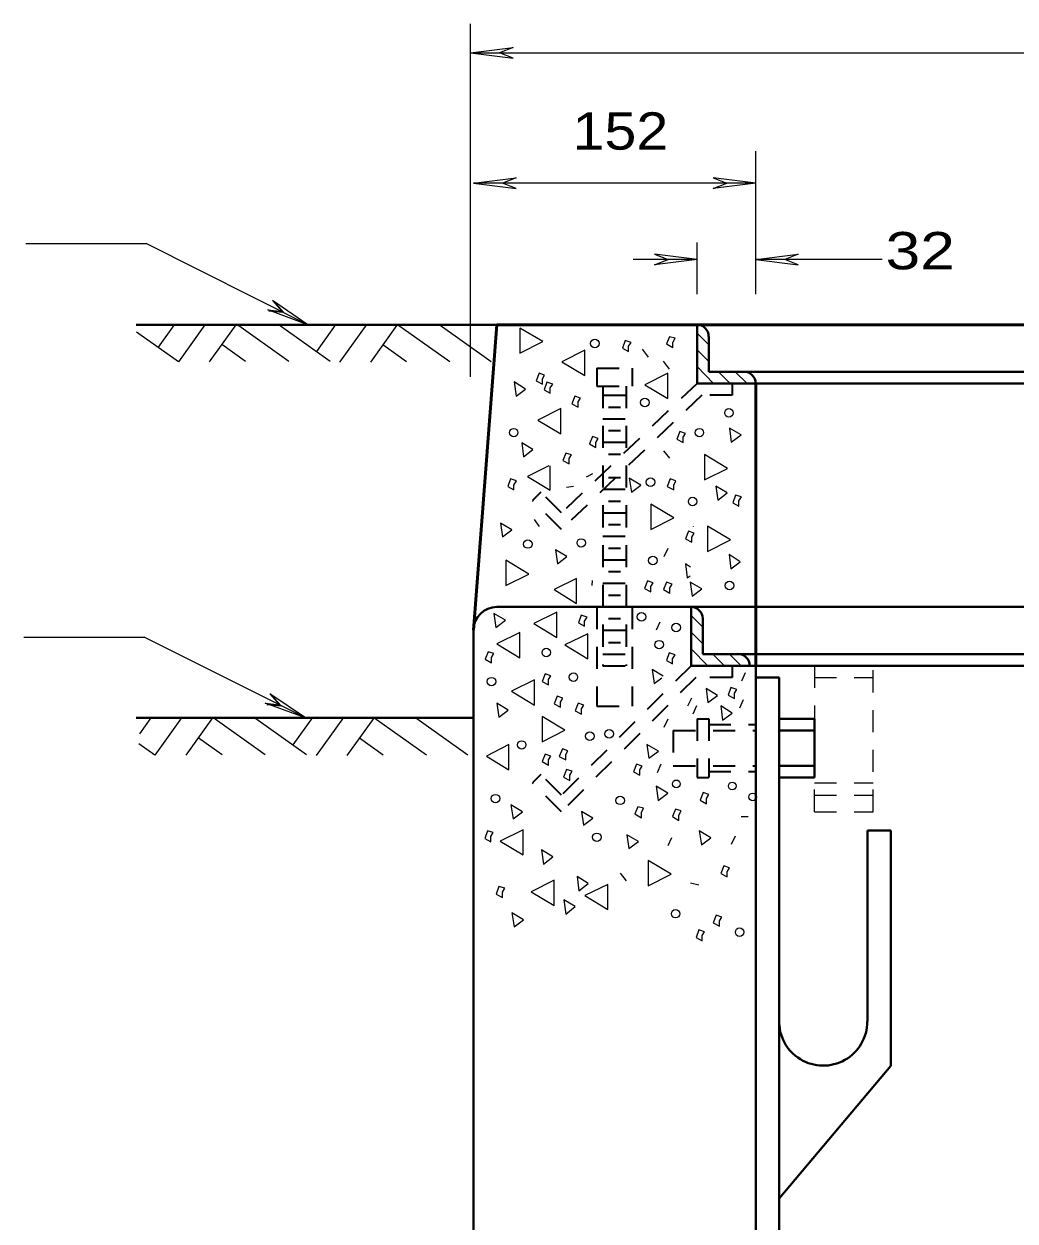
# Model space of a CAD drawing. Extents: x 312583 to 312853, y 144419 to 144586.
# Drawn here: x 312745.46 to 312765.66, y 144474.02 to 144498.4 of the extents above; entities that cross this region are included whole.
import ezdxf

# ---------------------------------------------------------------- set-up
doc = ezdxf.new("R2010")
doc.units = 0
doc.header["$LTSCALE"] = 0.3
doc.linetypes.add('SHORT_DASHED', pattern=[2.7, 1.5, -1.2])
doc.layers.add('1', color=7, linetype='Continuous', lineweight=40)
doc.layers.add('2', color=7, linetype='Continuous', lineweight=13)

msp = doc.modelspace()

# ---------------------------------------------------------------- linework, layer by layer
at = {"layer": '1'}
for p, q in [((312747.749, 144492.2754), (312755.1014, 144492.2754)), ((312759.18, 144492.2754), (312759.18, 144491.0794)), ((312759.4177, 144492.0377), (312759.4177, 144491.3171)), ((312759.4177, 144491.3171), (312778.5844, 144491.3171)), ((312759.18, 144491.0794), (312778.822, 144491.0794)), ((312755.1014, 144486.5254), (312782.893, 144486.5254)), ((312759.0574, 144486.5254), (312759.0574, 144485.3294)), ((312759.295, 144486.2877), (312759.295, 144485.5671)), ((312759.295, 144485.5671), (312778.5844, 144485.5671)), ((312759.0574, 144485.3294), (312778.822, 144485.3294)), ((312760.376, 144485.3294), (312760.376, 144443.4004)), ((312760.376, 144485.0917), (312760.8514, 144485.0917)), ((312760.8514, 144485.0917), (312760.8514, 144454.4251)), ((312747.749, 144484.2637), (312754.626, 144484.2637)), ((312760.8514, 144484.2484), (312761.572, 144484.2484)), ((312761.572, 144484.2484), (312761.572, 144483.0524)), ((312760.8514, 144484.0107), (312761.572, 144484.0107)), ((312760.8514, 144483.2901), (312761.572, 144483.2901)), ((312760.8514, 144483.0524), (312761.572, 144483.0524)), ((312762.653, 144481.9714), (312762.653, 144478.0844)), ((312762.653, 144481.9714), (312763.1284, 144481.9714)), ((312763.1284, 144481.9714), (312763.1284, 144477.1797)), ((312760.8514, 144474.4734), (312763.1284, 144477.1797))]:
    msp.add_line(p, q, dxfattribs=at)
at = {"layer": '1', "lineweight": 53}
for p, q in [((312754.626, 144486.0501), (312755.1014, 144492.2754)), ((312755.1014, 144492.2754), (312782.893, 144492.2754)), ((312760.376, 144491.0794), (312760.376, 144485.3294))]:
    msp.add_line(p, q, dxfattribs=at)
at = {"layer": '1', "lineweight": 13}
for p, q in [((312758.0607, 144491.7771), (312758.1834, 144491.6161)), ((312758.49, 144491.5317), (312758.6127, 144491.3707)), ((312758.4977, 144489.7071), (312758.6204, 144489.5537)), ((312756.19, 144488.9021), (312756.19, 144489.4004)), ((312756.926, 144489.1781), (312757.0564, 144489.2471)), ((312756.5197, 144488.9634), (312756.6654, 144488.9864)), ((312755.8604, 144488.3041), (312755.96, 144488.1661)), ((312759.1034, 144488.1737), (312759.1034, 144488.1661)), ((312758.582, 144487.7137), (312758.5054, 144487.5451)), ((312758.9807, 144487.1157), (312759.042, 144487.1617)), ((312757.041, 144486.9624), (312757.0487, 144487.0621)), ((312758.421, 144486.2187), (312758.3444, 144486.0501)), ((312760.1614, 144485.1837), (312760.0847, 144485.0151)), ((312758.306, 144484.9691), (312758.4594, 144485.0841)), ((312759.065, 144484.6701), (312758.9884, 144484.5014)), ((312759.1724, 144484.5091), (312759.0957, 144484.3404)), ((312760.123, 144484.6317), (312760.0464, 144484.4631)), ((312758.582, 144484.2407), (312758.5054, 144484.0721)), ((312758.444, 144483.3207), (312758.3674, 144483.1444)), ((312760.077, 144482.2551), (312760.2227, 144482.2551)), ((312758.6587, 144481.8257), (312758.582, 144481.6571)), ((312759.9544, 144481.8564), (312759.8777, 144481.6877)), ((312757.616, 144481.1051), (312757.7387, 144480.9441)), ((312759.0497, 144480.9057), (312759.2184, 144480.8674))]:
    msp.add_line(p, q, dxfattribs=at)
at = {"layer": '1', "linetype": 'SHORT_DASHED', "lineweight": 35}
for p, q in [((312757.1407, 144491.3861), (312757.1407, 144491.0257)), ((312757.1407, 144491.3861), (312757.8614, 144491.3861)), ((312757.8614, 144491.3861), (312757.8614, 144491.0257)), ((312759.18, 144491.0794), (312756.42, 144488.4421)), ((312757.1407, 144491.0257), (312757.8614, 144491.0257)), ((312757.2634, 144491.0257), (312757.2634, 144485.3294)), ((312757.7387, 144491.0257), (312757.7387, 144485.3294)), ((312759.893, 144491.0794), (312759.893, 144490.8417)), ((312759.2797, 144490.8417), (312756.42, 144488.1047)), ((312757.2634, 144490.8417), (312757.7387, 144490.8417)), ((312759.893, 144490.8417), (312759.2797, 144490.8417)), ((312757.3784, 144490.5964), (312757.6237, 144490.5964)), ((312757.2634, 144490.3587), (312757.7387, 144490.3587)), ((312757.3784, 144490.1211), (312757.6237, 144490.1211)), ((312757.2634, 144489.8834), (312757.7387, 144489.8834)), ((312757.3784, 144489.6381), (312757.6237, 144489.6381)), ((312757.3784, 144489.1627), (312757.6237, 144489.1627)), ((312755.9984, 144488.8637), (312755.8297, 144488.6951)), ((312756.42, 144488.4421), (312755.9984, 144488.8637)), ((312757.2634, 144488.9251), (312757.7387, 144488.9251)), ((312756.42, 144488.1047), (312755.8297, 144488.6951)), ((312757.3784, 144488.6797), (312757.6237, 144488.6797)), ((312757.2634, 144488.4421), (312757.7387, 144488.4421)), ((312757.3784, 144488.2044), (312757.6237, 144488.2044)), ((312757.2634, 144487.9667), (312757.7387, 144487.9667)), ((312757.3784, 144487.7214), (312757.6237, 144487.7214)), ((312757.2634, 144487.4837), (312757.7387, 144487.4837)), ((312757.3784, 144487.2461), (312757.6237, 144487.2461)), ((312757.2634, 144487.0084), (312757.7387, 144487.0084)), ((312757.3784, 144486.7631), (312757.6237, 144486.7631)), ((312757.1407, 144486.5254), (312757.1407, 144484.5014)), ((312757.2634, 144486.5254), (312757.7387, 144486.5254)), ((312757.8614, 144486.5254), (312757.8614, 144484.5014)), ((312757.3784, 144486.2877), (312757.6237, 144486.2877)), ((312757.2634, 144486.0501), (312757.7387, 144486.0501)), ((312757.3784, 144485.8047), (312757.6237, 144485.8047)), ((312757.2634, 144485.5671), (312757.7387, 144485.5671)), ((312759.0574, 144485.3294), (312756.42, 144482.6921)), ((312757.2634, 144485.3294), (312757.7387, 144485.3294)), ((312759.893, 144485.3294), (312759.893, 144485.0917)), ((312759.157, 144485.0917), (312756.42, 144482.3547)), ((312759.893, 144485.0917), (312759.157, 144485.0917)), ((312757.1407, 144484.5014), (312757.8614, 144484.5014)), ((312759.18, 144484.2484), (312759.18, 144483.0524)), ((312759.18, 144484.2484), (312759.4177, 144484.2484)), ((312759.4177, 144484.2484), (312759.4177, 144483.0524)), ((312758.697, 144484.0107), (312758.697, 144483.2901)), ((312758.697, 144484.0107), (312760.376, 144484.0107)), ((312759.4177, 144484.1334), (312760.376, 144484.1334)), ((312758.697, 144483.2901), (312760.376, 144483.2901)), ((312755.9984, 144483.1137), (312755.8297, 144482.9451)), ((312756.42, 144482.3547), (312755.8297, 144482.9451)), ((312756.42, 144482.6921), (312755.9984, 144483.1137)), ((312759.18, 144483.0524), (312759.4177, 144483.0524)), ((312759.4177, 144483.1751), (312760.376, 144483.1751))]:
    msp.add_line(p, q, dxfattribs=at)
at = {"layer": '1', "linetype": 'SHORT_DASHED', "lineweight": 25}
for p, q in [((312761.572, 144485.3294), (312761.572, 144484.2484)), ((312762.768, 144482.3547), (312762.768, 144485.3294)), ((312761.572, 144485.0917), (312762.768, 144485.0917)), ((312761.572, 144482.3547), (312761.572, 144483.0524)), ((312761.572, 144482.9451), (312762.768, 144482.9451)), ((312761.572, 144482.6921), (312762.768, 144482.6921)), ((312761.572, 144482.3547), (312762.768, 144482.3547))]:
    msp.add_line(p, q, dxfattribs=at)
at = {"layer": '1', "lineweight": 13}
for points in [[(312755.569, 144492.2064), (312755.569, 144491.6927), (312756.0367, 144491.9304)], [(312758.6894, 144491.9151), (312758.7354, 144491.9994), (312758.6204, 144492.0301), (312758.559, 144491.8844), (312758.6894, 144491.8077)], [(312756.8954, 144491.2404), (312756.8954, 144491.7541), (312756.4277, 144491.5164)], [(312757.7847, 144491.8384), (312757.8384, 144491.9151), (312757.7157, 144491.9534), (312757.662, 144491.8001), (312757.7847, 144491.7311)], [(312756.029, 144491.1714), (312756.075, 144491.2481), (312755.96, 144491.2864), (312755.8987, 144491.1331), (312756.029, 144491.0641)], [(312758.582, 144490.7727), (312758.582, 144491.2864), (312758.1144, 144491.0487)], [(312755.4924, 144490.8187), (312755.684, 144490.9644), (312755.454, 144491.1101)], [(312756.19, 144490.9874), (312756.2437, 144491.0641), (312756.121, 144491.1024), (312756.0674, 144490.9491), (312756.19, 144490.8801)], [(312756.7574, 144490.7037), (312756.8034, 144490.7804), (312756.6884, 144490.8187), (312756.627, 144490.6654), (312756.7574, 144490.5964)], [(312756.4047, 144490.0521), (312756.4047, 144490.5657), (312755.937, 144490.3281)], [(312758.8964, 144489.9831), (312758.9424, 144490.0597), (312758.8274, 144490.0981), (312758.766, 144489.9447), (312758.8964, 144489.8757)], [(312759.8777, 144489.8834), (312760.077, 144490.0291), (312759.8394, 144490.1671)], [(312755.6457, 144489.5844), (312755.8374, 144489.7301), (312755.6074, 144489.8681)], [(312757.1177, 144489.8757), (312757.1637, 144489.9601), (312757.0487, 144489.9984), (312756.9874, 144489.8451), (312757.1177, 144489.7761)], [(312756.5734, 144489.5461), (312756.6194, 144489.6227), (312756.5044, 144489.6611), (312756.443, 144489.5077), (312756.5734, 144489.4387)], [(312759.3334, 144489.6304), (312759.3334, 144489.1167), (312759.801, 144489.3467)], [(312755.4464, 144489.0094), (312755.5, 144489.0937), (312755.3774, 144489.1321), (312755.3237, 144488.9787), (312755.4464, 144488.9097)], [(312757.846, 144488.8637), (312758.0377, 144489.0094), (312757.8, 144489.1474)], [(312758.7047, 144489.0094), (312758.7507, 144489.0937), (312758.6357, 144489.1321), (312758.5744, 144488.9787), (312758.7047, 144488.9097)], [(312759.6017, 144488.7027), (312759.7934, 144488.8484), (312759.5634, 144488.9864)], [(312760.031, 144488.6874), (312760.0847, 144488.7717), (312759.962, 144488.8024), (312759.9084, 144488.6491), (312760.031, 144488.5801)], [(312758.237, 144488.6184), (312758.237, 144488.1047), (312758.7047, 144488.3424)], [(312755.2164, 144487.9514), (312755.408, 144488.0971), (312755.178, 144488.2351)], [(312759.0727, 144487.9437), (312759.1187, 144488.0281), (312759.0037, 144488.0664), (312758.9424, 144487.9131), (312759.0727, 144487.8441)], [(312759.3947, 144488.1737), (312759.3947, 144487.6524), (312759.8624, 144487.8901)], [(312756.3357, 144487.4071), (312756.5274, 144487.5527), (312756.2974, 144487.6907)], [(312759.87, 144487.2997), (312760.0617, 144487.4454), (312759.8317, 144487.5911)], [(312755.2854, 144487.4761), (312755.2854, 144486.9624), (312755.753, 144487.1924)], [(312756.7267, 144486.5944), (312756.7267, 144487.1081), (312756.2667, 144486.8781)], [(312758.237, 144486.9394), (312758.283, 144487.0161), (312758.168, 144487.0544), (312758.1067, 144486.9011), (312758.237, 144486.8321)], [(312758.628, 144486.9164), (312758.674, 144486.9931), (312758.559, 144487.0314), (312758.4977, 144486.8781), (312758.628, 144486.8091)], [(312759.0804, 144486.7477), (312759.2797, 144486.8934), (312759.042, 144487.0314)], [(312755.0784, 144486.1037), (312755.2777, 144486.2571), (312755.04, 144486.3951)], [(312756.3204, 144485.9044), (312756.3204, 144486.4181), (312755.8527, 144486.1881)], [(312756.8877, 144486.2341), (312756.9414, 144486.3184), (312756.8187, 144486.3567), (312756.765, 144486.2034), (312756.8877, 144486.1344)], [(312755.569, 144485.4904), (312755.569, 144486.0041), (312755.1014, 144485.7741)], [(312756.9567, 144485.4674), (312756.9567, 144485.9811), (312756.489, 144485.7511)], [(312754.994, 144485.4981), (312755.04, 144485.5747), (312754.925, 144485.6131), (312754.8637, 144485.4597), (312754.994, 144485.3907)], [(312758.6817, 144485.4674), (312758.7354, 144485.5517), (312758.6127, 144485.5901), (312758.559, 144485.4367), (312758.6817, 144485.3677)], [(312756.1517, 144485.0457), (312756.1977, 144485.1224), (312756.0827, 144485.1607), (312756.0214, 144485.0074), (312756.1517, 144484.9384)], [(312755.868, 144484.5244), (312755.868, 144485.0381), (312755.4004, 144484.8081)], [(312759.9467, 144484.7697), (312759.9927, 144484.8464), (312759.87, 144484.8847), (312759.8164, 144484.7314), (312759.9467, 144484.6624)], [(312756.397, 144484.5857), (312756.443, 144484.6701), (312756.328, 144484.7084), (312756.2667, 144484.5551), (312756.397, 144484.4861)], [(312759.4024, 144484.5781), (312759.594, 144484.7237), (312759.364, 144484.8617)], [(312755.1397, 144484.2791), (312755.3314, 144484.4247), (312755.1014, 144484.5627)], [(312756.8264, 144484.4477), (312756.8724, 144484.5244), (312756.7574, 144484.5627), (312756.696, 144484.4094), (312756.8264, 144484.3404)], [(312759.7014, 144484.2177), (312759.893, 144484.3634), (312759.663, 144484.5091)], [(312756.0214, 144484.2944), (312756.0214, 144483.7807), (312756.489, 144484.0184)], [(312755.3467, 144483.2057), (312755.3467, 144483.7271), (312754.8867, 144483.4894)], [(312758.1987, 144483.4434), (312758.398, 144483.5891), (312758.1604, 144483.7271)], [(312756.1517, 144483.4127), (312756.1977, 144483.4894), (312756.0827, 144483.5277), (312756.0214, 144483.3744), (312756.1517, 144483.3054)], [(312756.5044, 144483.5201), (312756.5504, 144483.5967), (312756.4354, 144483.6351), (312756.374, 144483.4817), (312756.5044, 144483.4127)], [(312756.5887, 144483.0984), (312756.6347, 144483.1827), (312756.5197, 144483.2134), (312756.4584, 144483.0601), (312756.5887, 144482.9911)], [(312758.0147, 144483.2057), (312758.0607, 144483.2824), (312757.9457, 144483.3207), (312757.8844, 144483.1674), (312758.0147, 144483.0984)], [(312758.3904, 144482.5847), (312758.582, 144482.7304), (312758.3444, 144482.8761)], [(312759.3717, 144482.6231), (312759.4177, 144482.7074), (312759.3027, 144482.7457), (312759.2414, 144482.5924), (312759.3717, 144482.5157)], [(312755.431, 144482.2091), (312755.6227, 144482.3547), (312755.385, 144482.4927)], [(312758.0454, 144482.3394), (312758.0914, 144482.4237), (312757.9764, 144482.4544), (312757.915, 144482.3087), (312758.0454, 144482.2321)], [(312756.8647, 144482.0787), (312757.0564, 144482.2244), (312756.8264, 144482.3624)], [(312758.812, 144482.2857), (312758.858, 144482.3701), (312758.743, 144482.4084), (312758.6817, 144482.2551), (312758.812, 144482.1784)], [(312754.9787, 144481.8487), (312755.0247, 144481.9331), (312754.9097, 144481.9637), (312754.856, 144481.8104), (312754.9787, 144481.7414)], [(312755.638, 144481.4731), (312755.638, 144481.9867), (312755.1704, 144481.7567)], [(312759.272, 144481.6801), (312759.4637, 144481.8257), (312759.226, 144481.9637)], [(312757.7924, 144481.6034), (312757.984, 144481.7491), (312757.7464, 144481.8871)], [(312756.052, 144481.2891), (312756.2437, 144481.4347), (312756.0137, 144481.5804)], [(312758.1834, 144481.3581), (312758.1834, 144480.8444), (312758.651, 144481.0821)], [(312759.7934, 144481.1281), (312759.8394, 144481.2124), (312759.7244, 144481.2507), (312759.663, 144481.0974), (312759.7934, 144481.0284)], [(312756.7727, 144480.7447), (312756.9644, 144480.8904), (312756.7344, 144481.0361)], [(312755.2164, 144480.7141), (312755.2624, 144480.7984), (312755.1397, 144480.8291), (312755.086, 144480.6757), (312755.2164, 144480.6067)], [(312756.2667, 144480.4457), (312756.2667, 144480.9594), (312755.799, 144480.7217)], [(312757.363, 144480.3614), (312757.363, 144480.8751), (312756.8954, 144480.6451)], [(312756.5044, 144480.2694), (312756.696, 144480.4227), (312756.466, 144480.5607)], [(312755.454, 144480.0087), (312755.6457, 144480.1544), (312755.408, 144480.2924)], [(312759.64, 144480.1314), (312759.686, 144480.2081), (312759.571, 144480.2464), (312759.5097, 144480.0931), (312759.64, 144480.0241)], [(312759.2874, 144479.8324), (312759.3334, 144479.9091), (312759.2184, 144479.9474), (312759.1647, 144479.7941), (312759.2874, 144479.7251)]]:
    msp.add_lwpolyline(points, close=True, dxfattribs=at)
for points in [[(312756.1594, 144489.4004), (312755.7224, 144489.1857), (312756.19, 144488.9021)], [(312759.0497, 144487.3381), (312758.9424, 144487.4071), (312758.9807, 144487.1157)], [(312758.49, 144485.1147), (312758.2677, 144485.2527), (312758.306, 144484.9691)]]:
    msp.add_lwpolyline(points, dxfattribs=at)
at = {"layer": '1'}
msp.add_lwpolyline([(312754.626, 144486.0501), (312754.626, 144443.4004), (312783.376, 144443.4004)], dxfattribs=at)
at = {"layer": '1', "lineweight": 13}
for centre, radius in [((312757.099, 144491.8928), 0.0865), ((312758.1177, 144490.6892), 0.0865), ((312759.8302, 144490.4802), 0.0865), ((312755.4439, 144490.0758), 0.0865), ((312759.2284, 144490.0758), 0.0865), ((312758.2327, 144489.0686), 0.0865), ((312759.0894, 144488.6747), 0.0865), ((312755.7324, 144487.8065), 0.0865), ((312756.821, 144487.8295), 0.0865), ((312758.2796, 144487.4711), 0.0865), ((312759.8417, 144486.9612), 0.0865), ((312758.0477, 144486.3249), 0.0865), ((312758.754, 144486.1055), 0.0865), ((312756.109, 144485.5966), 0.0865), ((312758.4071, 144485.7576), 0.0865), ((312756.661, 144485.0944), 0.0865), ((312754.9925, 144485.0053), 0.0865), ((312756.9945, 144483.8946), 0.0865), ((312757.3884, 144483.9406), 0.0865), ((312755.6068, 144483.7154), 0.0865), ((312758.7584, 144482.9221), 0.0784), ((312759.8969, 144482.878), 0.0784), ((312755.073, 144482.621), 0.0865), ((312760.3147, 144482.6557), 0.0784), ((312757.6145, 144482.5855), 0.0865), ((312757.1373, 144481.8332), 0.0865), ((312758.7435, 144480.2778), 0.0865), ((312760.0478, 144479.9012), 0.0865)]:
    msp.add_circle(centre, radius, dxfattribs=at)
at = {"layer": '1'}
for centre, radius, start, end in [((312759.1762, 144492.0368), 0.2396, 0, 90), ((312760.1345, 144491.0784), 0.2396, 0, 90), ((312755.1033, 144486.0472), 0.4792, 90, 180), ((312759.0564, 144486.2868), 0.2396, 0, 90), ((312760.0147, 144485.3284), 0.2396, 0, 90), ((312761.7512, 144478.081), 0.8984, 178.12864, 359.96943)]:
    msp.add_arc(centre, radius, start, end, dxfattribs=at)
at = {"layer": '2'}
for p, q in [((312754.5647, 144491.2097), (312754.5647, 144498.4011)), ((312754.5647, 144497.8107), (312755.431, 144497.9181)), ((312754.5647, 144497.8107), (312783.376, 144497.8107)), ((312754.5647, 144497.8107), (312755.431, 144497.7034)), ((312755.431, 144497.9181), (312755.155, 144497.8107)), ((312755.431, 144497.7034), (312755.155, 144497.8107)), ((312760.376, 144492.8964), (312760.376, 144495.8097)), ((312754.626, 144495.1581), (312755.4924, 144495.2654)), ((312760.376, 144495.1581), (312754.626, 144495.1581)), ((312754.626, 144495.1581), (312755.4924, 144495.0507)), ((312755.4924, 144495.2654), (312755.2164, 144495.1581)), ((312755.4924, 144495.0507), (312755.2164, 144495.1581)), ((312759.5097, 144495.2654), (312759.7857, 144495.1581)), ((312760.376, 144495.1581), (312759.5097, 144495.2654)), ((312759.5097, 144495.0507), (312759.7857, 144495.1581)), ((312760.376, 144495.1581), (312759.5097, 144495.0507)), ((312745.5027, 144493.9314), (312747.956, 144493.9314)), ((312751.2527, 144492.2754), (312747.956, 144493.9314)), ((312759.18, 144492.8964), (312759.18, 144493.9467)), ((312758.3137, 144493.7091), (312758.5897, 144493.6017)), ((312759.18, 144493.6017), (312758.3137, 144493.7091)), ((312760.376, 144493.6017), (312761.2424, 144493.7091)), ((312761.2424, 144493.7091), (312760.9664, 144493.6017)), ((312759.18, 144493.6017), (312757.8767, 144493.6017)), ((312758.3137, 144493.4944), (312758.5897, 144493.6017)), ((312759.18, 144493.6017), (312758.3137, 144493.4944)), ((312762.952, 144493.6017), (312760.376, 144493.6017)), ((312760.376, 144493.6017), (312761.2424, 144493.4944)), ((312761.2424, 144493.4944), (312760.9664, 144493.6017)), ((312750.532, 144492.7661), (312750.7237, 144492.5437)), ((312751.2527, 144492.2754), (312750.532, 144492.7661)), ((312750.555, 144492.7507), (312750.7467, 144492.5284)), ((312750.4324, 144492.5744), (312750.7237, 144492.5437)), ((312751.2527, 144492.2754), (312750.4324, 144492.5744)), ((312750.4554, 144492.5591), (312750.7467, 144492.5284)), ((312748.5234, 144492.2754), (312748.2014, 144491.8154)), ((312748.232, 144492.2754), (312748.462, 144492.2754)), ((312749.152, 144492.2754), (312748.6154, 144491.5164)), ((312749.7807, 144492.2754), (312749.2364, 144491.5164)), ((312750.8617, 144491.5241), (312749.796, 144492.2831)), ((312751.705, 144491.5241), (312750.6624, 144492.2677)), ((312751.82, 144492.2831), (312751.429, 144491.7311)), ((312752.4487, 144492.2831), (312751.8967, 144491.5087)), ((312753.062, 144492.2677), (312752.5254, 144491.5087)), ((312754.143, 144491.5164), (312753.0774, 144492.2754)), ((312754.9864, 144491.5164), (312753.9437, 144492.2601)), ((312748.6154, 144491.5164), (312747.7567, 144492.1221)), ((312759.4177, 144491.8614), (312759.18, 144492.0991)), ((312749.98, 144491.5241), (312749.497, 144491.8691)), ((312753.2614, 144491.5164), (312752.7784, 144491.8614)), ((312759.4177, 144491.5241), (312759.18, 144491.7617)), ((312759.5174, 144491.0794), (312759.18, 144491.4244)), ((312759.8547, 144491.0794), (312759.617, 144491.3171)), ((312760.1997, 144491.0794), (312759.9544, 144491.3171)), ((312759.295, 144486.1114), (312759.0574, 144486.3491)), ((312745.4644, 144485.9121), (312747.9177, 144485.9121)), ((312751.199, 144484.2637), (312747.9177, 144485.9121)), ((312759.295, 144485.7741), (312759.0574, 144486.0117)), ((312759.4024, 144485.3294), (312759.0574, 144485.6744)), ((312759.7397, 144485.3294), (312759.502, 144485.5671)), ((312760.077, 144485.3294), (312759.8394, 144485.5671)), ((312750.4784, 144484.7544), (312750.67, 144484.5321)), ((312751.199, 144484.2637), (312750.4784, 144484.7544)), ((312750.509, 144484.7314), (312750.7084, 144484.5091)), ((312750.3787, 144484.5627), (312750.67, 144484.5321)), ((312751.199, 144484.2637), (312750.3787, 144484.5627)), ((312750.417, 144484.5397), (312750.7084, 144484.5091)), ((312748.048, 144484.2637), (312747.818, 144483.9417)), ((312748.6767, 144484.2637), (312748.1324, 144483.5047)), ((312749.3054, 144484.2637), (312748.761, 144483.5047)), ((312750.3787, 144483.5124), (312749.313, 144484.2714)), ((312751.222, 144483.5124), (312750.187, 144484.2484)), ((312751.3447, 144484.2714), (312750.946, 144483.7194)), ((312751.9734, 144484.2714), (312751.4214, 144483.4971)), ((312752.5867, 144484.2561), (312752.0424, 144483.4971)), ((312753.6677, 144483.5047), (312752.5944, 144484.2637)), ((312754.511, 144483.5047), (312753.4684, 144484.2484)), ((312748.1324, 144483.5047), (312747.8027, 144483.7347)), ((312749.5047, 144483.5124), (312749.014, 144483.8574)), ((312752.786, 144483.5047), (312752.303, 144483.8497))]:
    msp.add_line(p, q, dxfattribs=at)
at = {"layer": '2', "lineweight": 35}
msp.add_line((312759.18, 144491.1407), (312759.1724, 144491.1407), dxfattribs=at)

# ---------------------------------------------------------------- texts
at = {"layer": '2'}
for s, width, p in [('152 ', 1.15, (312756.6438, 144495.8404)), (' 32 ', 1.25, (312762.6689, 144493.403))]:
    msp.add_text(s, height=0.76, dxfattribs=dict(at, width=width)).set_placement(p)

doc.saveas('drawing.dxf')
